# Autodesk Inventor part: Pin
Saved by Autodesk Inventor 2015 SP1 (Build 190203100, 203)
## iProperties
Created: 2011-06
Part Number: Pin
Material: Steel
Document SubType Name: Modeling
Designer: Guilherme Augusto Franco de Souza
Density: 7.85 g/cm^3
Mass: 25.4879 g
Surface Area: 15.3496 cm^2
Volume: 3.24687 cm^3
Description: Steel - DIN-20CrMoS4
Appearance: Steel
CustomPartVersion: 1
Author: Guilherme Augusto Franco de Souza
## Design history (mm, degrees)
sketch "Main Sketch"
  geometry: L1 (0, 0)-(39, 0) reference; L2 (0, 0)-(0, 7); L3 (3, 7)-(3, 5); L4 (0, 7)-(3, 7); L5 (39, 5)-(39, 0); L6 (3, 5)-(39, 5)
  constraints: 12 end point, 4 horizontal, 3 vertical
  dimensions: "d3" = 14 diameter of L4 L1 (derived); "d4" = 10 diameter of L6 L1 (derived)
revolve "Revolution1" sketch "Main Sketch" stored, may be unused: angle "d5" = 0 deg
chamfer "Chamfer1" distance "d6" = 1; stored, may be unused: second distance "d7" = 0.125, angle "d8" = 45 deg
chamfer "Chamfer2" distance "d9" = 1; stored, may be unused: second distance "d10" = 0.125, angle "d11" = 45 deg
node "Retaining Ring Groove1"
body "Solid1"
feature "iFeature27:1"
other parameters: "d0" = 0, "d1" = 0, "d2" = 0
